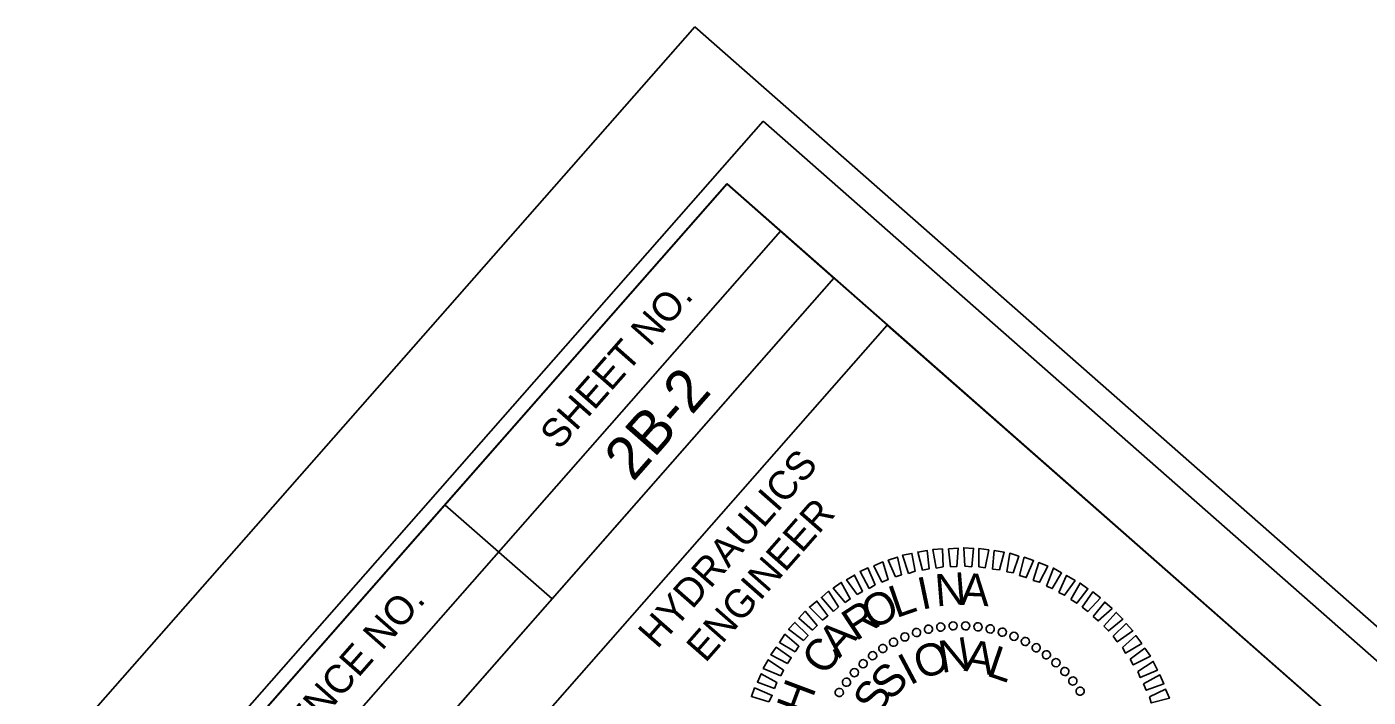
# Model space of a CAD drawing. Extents: x 2189835 to 2191772, y 387461 to 389531.
# Drawn here: x 2190828.7 to 2191064.5, y 389330.6 to 389448.4 of the extents above; entities that cross this region are included whole.
import ezdxf

# ---------------------------------------------------------------- set-up
doc = ezdxf.new("R2010")
doc.units = 0
for name, color, linetype in [('Sheet Cutting Line CELL', 7, 'Continuous'), ('Sheet Data Field CELL', 7, 'Continuous'), ('Sheet Plan CELL', 7, 'Continuous'), ('Sheet Plan Layout CELL', 7, 'Continuous'), ('Sheet Plot Border Inside CELL', 7, 'Continuous'), ('Sheet Plot Border Outside CELL', 7, 'Continuous'), ('Sheet Professional Seal CELL', 7, 'Continuous')]:
    doc.layers.add(name, color=color, linetype=linetype)

msp = doc.modelspace()

# ---------------------------------------------------------------- linework, layer by layer
at = {"layer": 'Sheet Cutting Line CELL'}
msp.add_line((2190946.11, 389448.37), (2189834.54, 388184.02), dxfattribs=at)
at = {"layer": 'Sheet Plan CELL'}
for p, q in [((2190829.09, 389262.23), (2190961.19, 389412.46)), ((2190838.52, 389253.96), (2190970.58, 389404.21)), ((2190838.52, 389253.96), (2190970.58, 389404.21)), ((2190902.27, 389364.36), (2190921.08, 389347.89))]:
    msp.add_line(p, q, dxfattribs=at)
for points in [[(2190951.79, 389420.78), (2189961.36, 388294.21), (2190749.93, 387600.92), (2191740.35, 388727.47)], [(2190819.67, 389270.52), (2190951.79, 389420.78), (2190970.58, 389404.21), (2190838.52, 389253.96)], [(2190913.95, 389320.85), (2190979.96, 389395.96), (2191064.47, 389321.68), (2190998.45, 389246.57)]]:
    msp.add_lwpolyline(points, close=True, dxfattribs=at)
at = {"layer": 'Sheet Plan Layout CELL'}
msp.add_lwpolyline([(2190952.63, 389101.43), (2191110.61, 389281.13), (2190951.8, 389420.79), (2190793.79, 389241.07)], close=True, dxfattribs=at)
at = {"layer": 'Sheet Plot Border Inside CELL'}
msp.add_lwpolyline([(2190650.48, 387483.99), (2191750.47, 388735.2), (2190958.16, 389431.79), (2189858.14, 388180.58)], close=True, dxfattribs=at)
at = {"layer": 'Sheet Plot Border Outside CELL'}
msp.add_lwpolyline([(2190656.91, 387461.02), (2191768.48, 388725.38), (2190946.11, 389448.37), (2189834.54, 388184.02)], close=True, dxfattribs=at)
at = {"layer": 'Sheet Professional Seal CELL'}
for p, q in [((2190985.07, 389342.01), (2190985.07, 389342.01)), ((2190987.2, 389342.54), (2190987.2, 389342.54)), ((2190989.37, 389342.97), (2190989.37, 389342.97)), ((2190991.52, 389343.14), (2190991.52, 389343.14)), ((2190993.75, 389343.19), (2190993.75, 389343.19)), ((2190995.89, 389342.97), (2190995.89, 389342.97)), ((2190998.07, 389342.59), (2190998.07, 389342.59)), ((2191000.2, 389342.06), (2191000.2, 389342.06)), ((2190981.04, 389340.29), (2190981.04, 389340.29)), ((2190983.03, 389341.2), (2190983.03, 389341.2)), ((2191002.23, 389341.34), (2191002.23, 389341.34)), ((2191004.21, 389340.41), (2191004.21, 389340.41)), ((2190977.41, 389337.88), (2190977.41, 389337.88)), ((2190979.13, 389339.17), (2190979.13, 389339.17)), ((2191006.12, 389339.26), (2191006.12, 389339.26)), ((2191007.94, 389338.07), (2191007.94, 389338.07)), ((2190974.17, 389334.94), (2190974.17, 389334.94)), ((2190975.73, 389336.5), (2190975.73, 389336.5)), ((2191009.63, 389336.66), (2191009.63, 389336.66)), ((2191011.18, 389335.1), (2191011.18, 389335.1)), ((2190972.76, 389333.25), (2190972.76, 389333.25)), ((2191012.57, 389333.42), (2191012.57, 389333.42)), ((2190971.56, 389331.44), (2190971.56, 389331.44)), ((2191013.86, 389331.7), (2191013.86, 389331.7))]:
    msp.add_line(p, q, dxfattribs=at)
for points in [[(2190986.16, 389352.89), (2190985.3, 389356.09), (2190986.99, 389356.34), (2190987.31, 389353.14)], [(2190988.57, 389353.29), (2190987.97, 389356.55), (2190989.66, 389356.66), (2190989.76, 389353.52)], [(2190991.08, 389353.5), (2190990.72, 389356.66), (2190992.42, 389356.77), (2190992.17, 389353.53)], [(2190993.58, 389353.63), (2190993.4, 389356.84), (2190995.11, 389356.74), (2190994.8, 389353.5)], [(2190996.04, 389353.47), (2190996.07, 389356.7), (2190997.79, 389356.46), (2190997.15, 389353.3)], [(2190998.44, 389353.1), (2190998.75, 389356.35), (2191000.51, 389356.07), (2190999.65, 389352.97)], [(2190979, 389350.78), (2190977.6, 389353.66), (2190979.15, 389354.37), (2190980.13, 389351.25)], [(2190981.38, 389351.75), (2190980.12, 389354.65), (2190981.75, 389355.22), (2190982.45, 389352.07)], [(2190983.68, 389352.33), (2190982.65, 389355.56), (2190984.29, 389355.85), (2190984.85, 389352.76)], [(2191000.95, 389352.63), (2191001.48, 389355.89), (2191003.07, 389355.36), (2191002.06, 389352.45)], [(2191003.22, 389351.97), (2191004.04, 389355.17), (2191005.67, 389354.61), (2191004.38, 389351.62)], [(2191005.59, 389351.09), (2191006.62, 389354.25), (2191008.15, 389353.64), (2191006.71, 389350.78)], [(2190974.64, 389348.61), (2190972.8, 389351.22), (2190974.2, 389352.06), (2190975.6, 389349.17)], [(2190976.8, 389349.71), (2190975.19, 389352.65), (2190976.56, 389353.31), (2190977.82, 389350.35)], [(2191007.92, 389350.12), (2191009.16, 389353.28), (2191010.6, 389352.42), (2191008.94, 389349.69)], [(2191010.12, 389348.99), (2191011.48, 389351.98), (2191012.96, 389351.09), (2191011.11, 389348.52)], [(2190970.48, 389345.68), (2190968.37, 389348.13), (2190969.64, 389349.2), (2190971.38, 389346.48)], [(2190972.57, 389347.24), (2190970.45, 389349.75), (2190971.88, 389350.77), (2190973.45, 389347.86)], [(2191012.22, 389347.74), (2191013.84, 389350.65), (2191015.21, 389349.64), (2191013.26, 389347.1)], [(2191014.23, 389346.39), (2191016.07, 389349.1), (2191017.41, 389348.05), (2191015.19, 389345.67)], [(2190968.6, 389344.14), (2190966.28, 389346.43), (2190967.59, 389347.47), (2190969.54, 389344.91)], [(2191016.14, 389344.78), (2191018.17, 389347.32), (2191019.45, 389346.2), (2191017.04, 389343.99)], [(2190966.84, 389342.35), (2190964.39, 389344.5), (2190965.51, 389345.7), (2190967.66, 389343.22)], [(2191017.99, 389343.1), (2191020.2, 389345.48), (2191021.38, 389344.31), (2191018.82, 389342.23)], [(2190965.22, 389340.58), (2190962.61, 389342.53), (2190963.73, 389343.74), (2190966.05, 389341.45)], [(2191019.63, 389341.33), (2191021.96, 389343.54), (2191023.11, 389342.27), (2191020.37, 389340.35)], [(2190963.76, 389338.54), (2190960.99, 389340.23), (2190961.96, 389341.64), (2190964.44, 389339.54)], [(2191021.28, 389339.35), (2191023.63, 389341.42), (2191024.68, 389340.03), (2191021.81, 389338.35)], [(2190962.4, 389336.53), (2190959.47, 389338.04), (2190960.44, 389339.38), (2190963.08, 389337.53)], [(2191022.66, 389337.28), (2191025.19, 389339.18), (2191026.2, 389337.83), (2191023.19, 389336.28)], [(2190961.24, 389334.36), (2190958.17, 389335.65), (2190959.03, 389337.16), (2190961.74, 389335.32)], [(2191023.97, 389335.13), (2191026.69, 389336.87), (2191027.43, 389335.36), (2191024.4, 389334.03)], [(2190960.14, 389332.13), (2190957.13, 389333.24), (2190957.81, 389334.7), (2190960.57, 389333.15)], [(2191024.97, 389332.93), (2191027.88, 389334.5), (2191028.55, 389332.92), (2191025.47, 389331.83)], [(2190959.13, 389329.76), (2190956.09, 389330.69), (2190956.63, 389332.22), (2190959.73, 389330.9)], [(2191026.04, 389330.66), (2191028.86, 389331.98), (2191029.53, 389330.4), (2191026.36, 389329.59)]]:
    msp.add_lwpolyline(points, close=True, dxfattribs=at)
for centre, major_axis in [((2190983.04, 389341.19), (-0.279, 0.664)), ((2190985.09, 389341.95), (-0.22, 0.686)), ((2190987.2, 389342.53), (-0.16, 0.702)), ((2190989.35, 389342.92), (-0.098, 0.713)), ((2190991.53, 389343.12), (-0.035, 0.719)), ((2190993.72, 389343.13), (0.028, 0.719)), ((2190995.9, 389342.95), (0.09, 0.714)), ((2190998.06, 389342.58), (0.152, 0.704)), ((2191000.17, 389342.03), (0.213, 0.688)), ((2191002.23, 389341.29), (0.272, 0.667)), ((2190979.17, 389339.15), (-0.39, 0.605)), ((2190981.06, 389340.25), (-0.336, 0.637)), ((2191004.22, 389340.38), (0.329, 0.64)), ((2191006.12, 389339.29), (0.384, 0.609)), ((2190975.72, 389336.47), (-0.489, 0.528)), ((2190977.38, 389337.89), (-0.441, 0.569)), ((2191007.92, 389338.05), (0.435, 0.574)), ((2191009.6, 389336.65), (0.484, 0.533)), ((2190974.18, 389334.92), (-0.533, 0.484)), ((2191011.16, 389335.11), (0.528, 0.489)), ((2190972.78, 389333.23), (-0.574, 0.435)), ((2191012.57, 389333.44), (0.569, 0.441)), ((2191013.84, 389331.66), (0.605, 0.39)), ((2190971.53, 389331.43), (-0.609, 0.384))]:
    msp.add_ellipse(centre, major_axis=major_axis, ratio=0.999708, dxfattribs=at)

# ---------------------------------------------------------------- texts
at = {"layer": 'Sheet Data Field CELL'}
msp.add_text('2B-2', height=7.5, rotation=48.6794, dxfattribs=at).set_placement((2190935.28, 389368.3))
at = {"layer": 'Sheet Plan CELL'}
for s, height, p in [('SHEET NO.', 5, (2190922.29, 389373.86)), ('HYDRAULICS', 5, (2190939.53, 389338.93)), ('ENGINEER', 5, (2190948, 389336.5)), ('PROJECT REFERENCE NO.', 5.0001, (2190840.88, 389281.44))]:
    msp.add_text(s, height=height, rotation=48.6794, dxfattribs=at).set_placement(p)
at = {"layer": 'Sheet Professional Seal CELL'}
for s, rotation, p in [('I', 11.8215, (2190985.98, 389345.93)), ('N', 4.6203, (2190988.56, 389346.53)), ('A', 357.4185, (2190992.73, 389346.8)), ('O', 26.2225, (2190977.22, 389342.37)), ('L', 19.0223, (2190981.51, 389344.46)), ('R', 33.4225, (2190974.45, 389340.34)), ('A', 47.8217, (2190971.53, 389337.32)), ('C', 55.0213, (2190969.15, 389334.15)), ('O', 18.6349, (2190985.77, 389333.62)), ('N', 9.278, (2190989.48, 389334.82)), ('A', 350.5616, (2190993.32, 389335.26)), ('L', 341.2022, (2190997.2, 389334.45)), ('I', 27.991, (2190983.93, 389332.58)), ('S', 46.7018, (2190980.57, 389329.8)), ('H', 69.4209, (2190965.65, 389327.11)), ('S', 56.057, (2190978.23, 389327.06))]:
    msp.add_text(s, height=5.64, rotation=rotation, dxfattribs=at).set_placement(p)

doc.saveas('drawing.dxf')
